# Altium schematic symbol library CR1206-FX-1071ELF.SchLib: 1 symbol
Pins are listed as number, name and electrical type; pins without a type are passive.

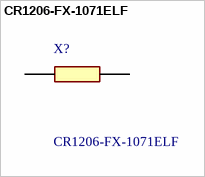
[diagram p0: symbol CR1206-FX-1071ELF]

## CR1206-FX-1071ELF
designator X?
Thick Film Resistors - SMD 1.07K 1%; Manufacturer_Name: Bourns; Geometry.Height: 0.75mm
footprint RESC3216X75N
pins: 1, 2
